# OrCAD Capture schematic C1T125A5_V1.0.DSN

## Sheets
1 001_MainChip: size A4; title: Telink-Semi; rev: V1.0A; note: C1T125A5
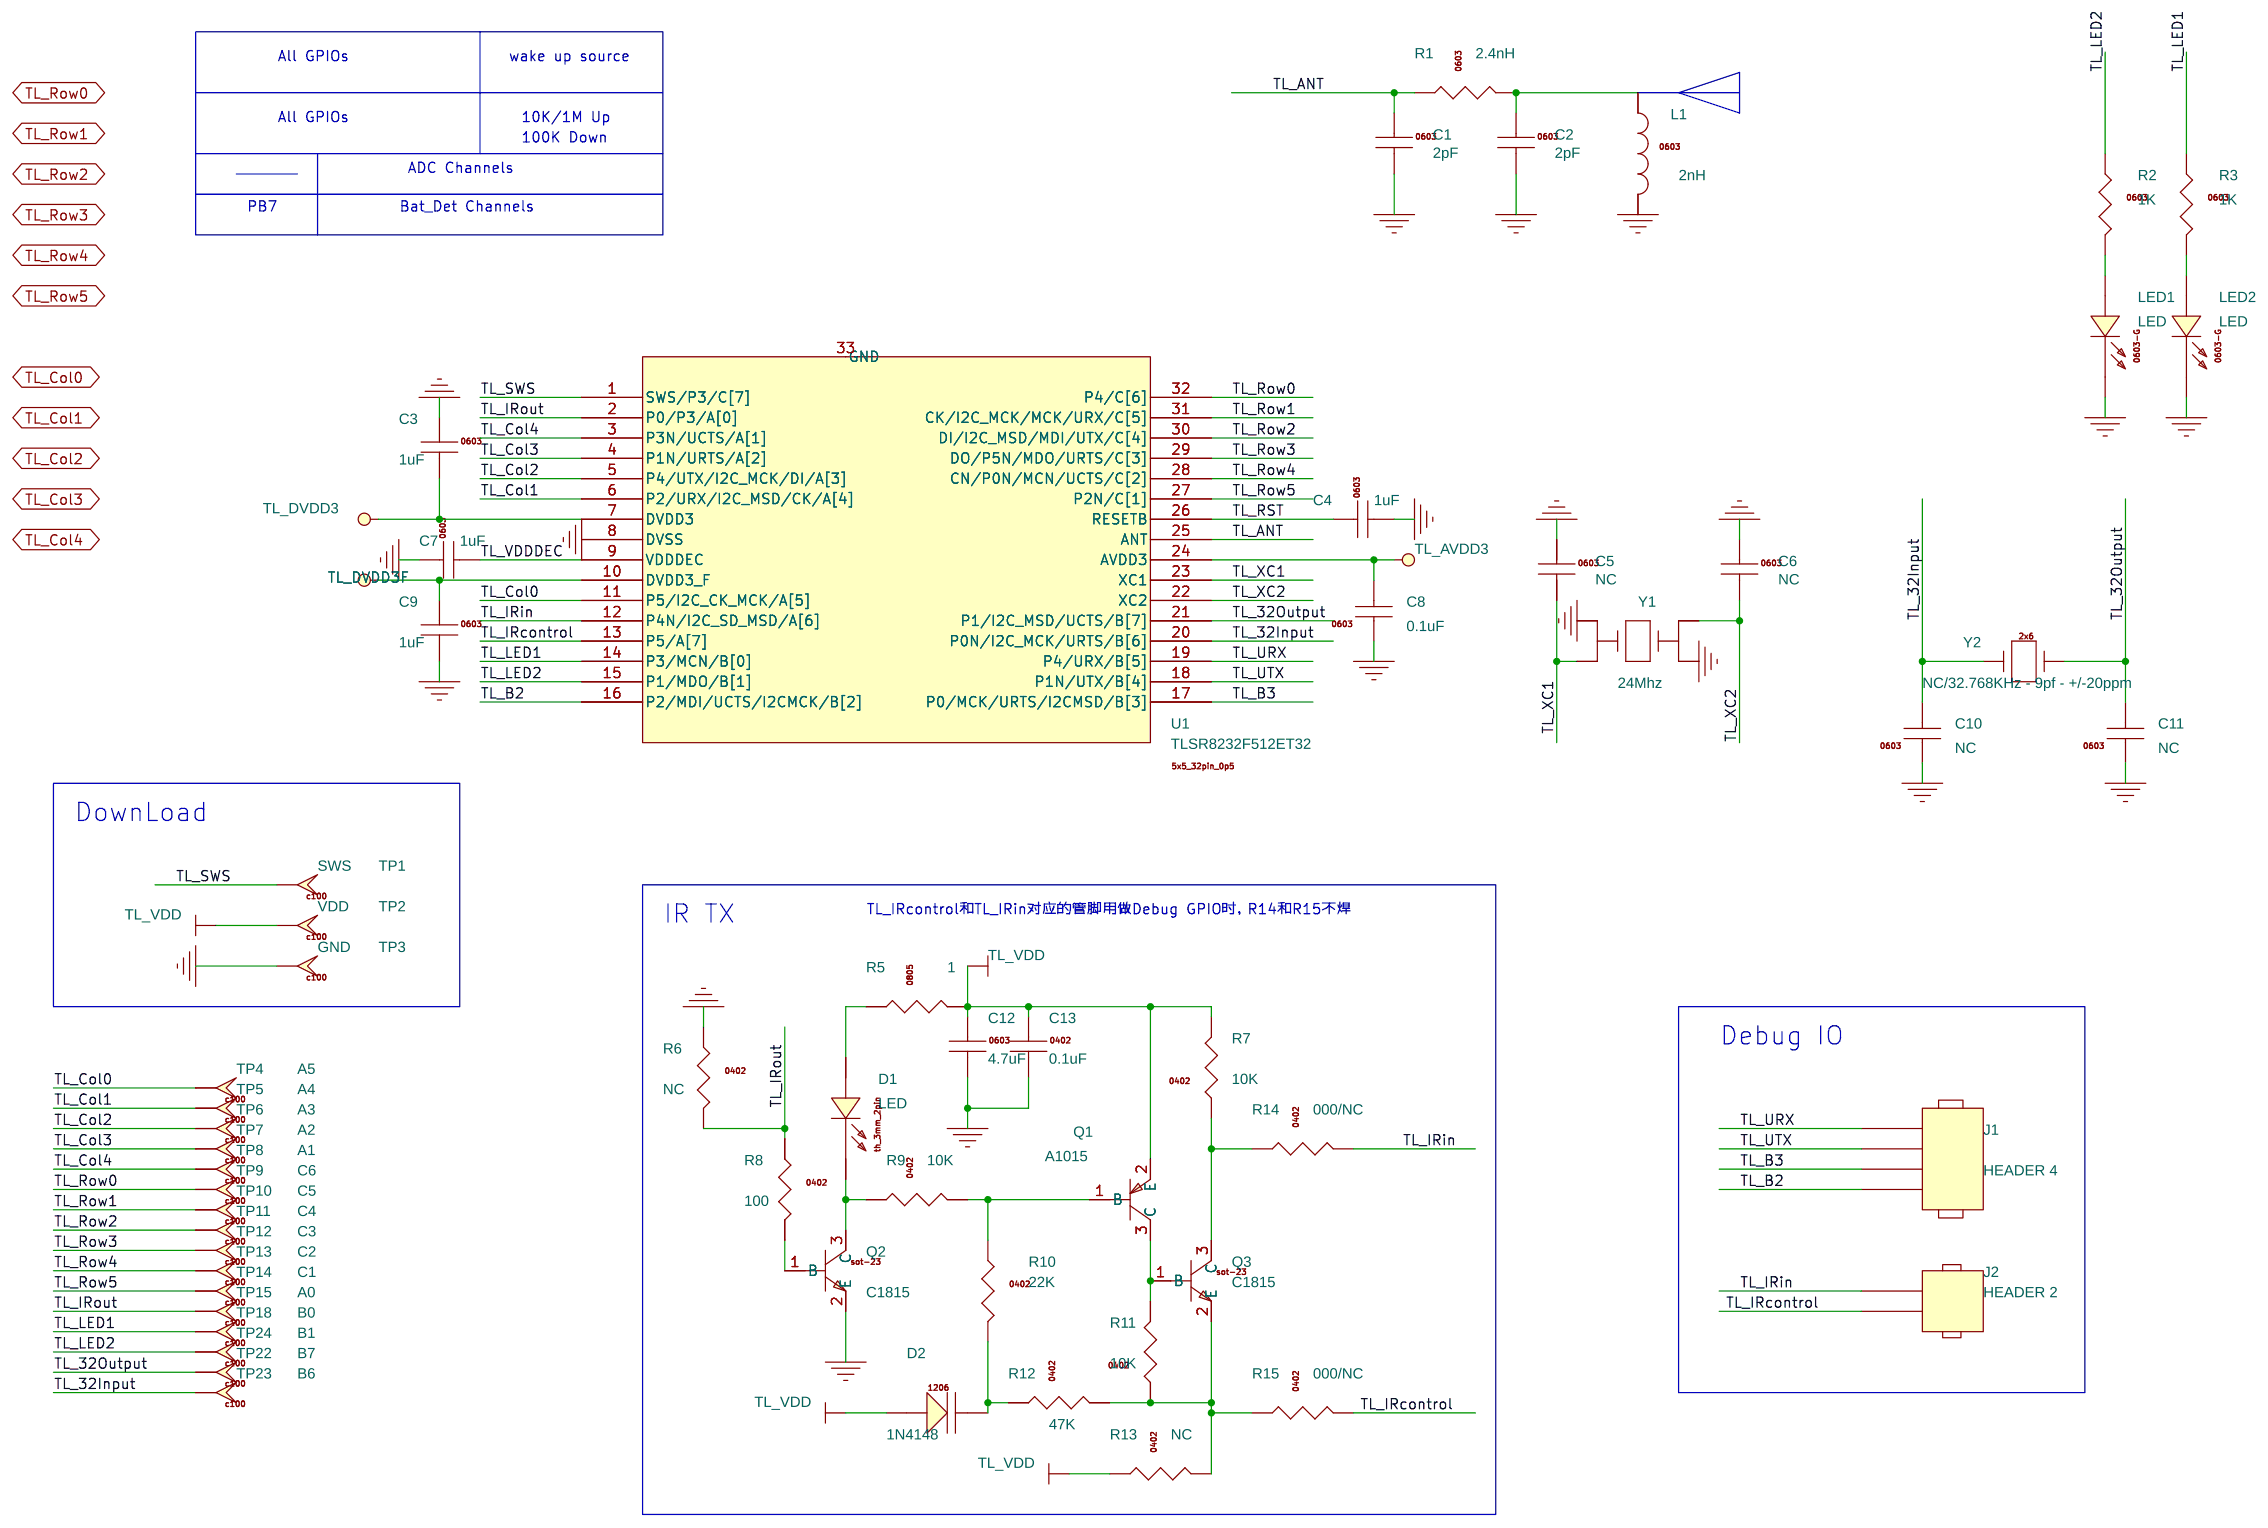
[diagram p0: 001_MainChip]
2 002_key: size A
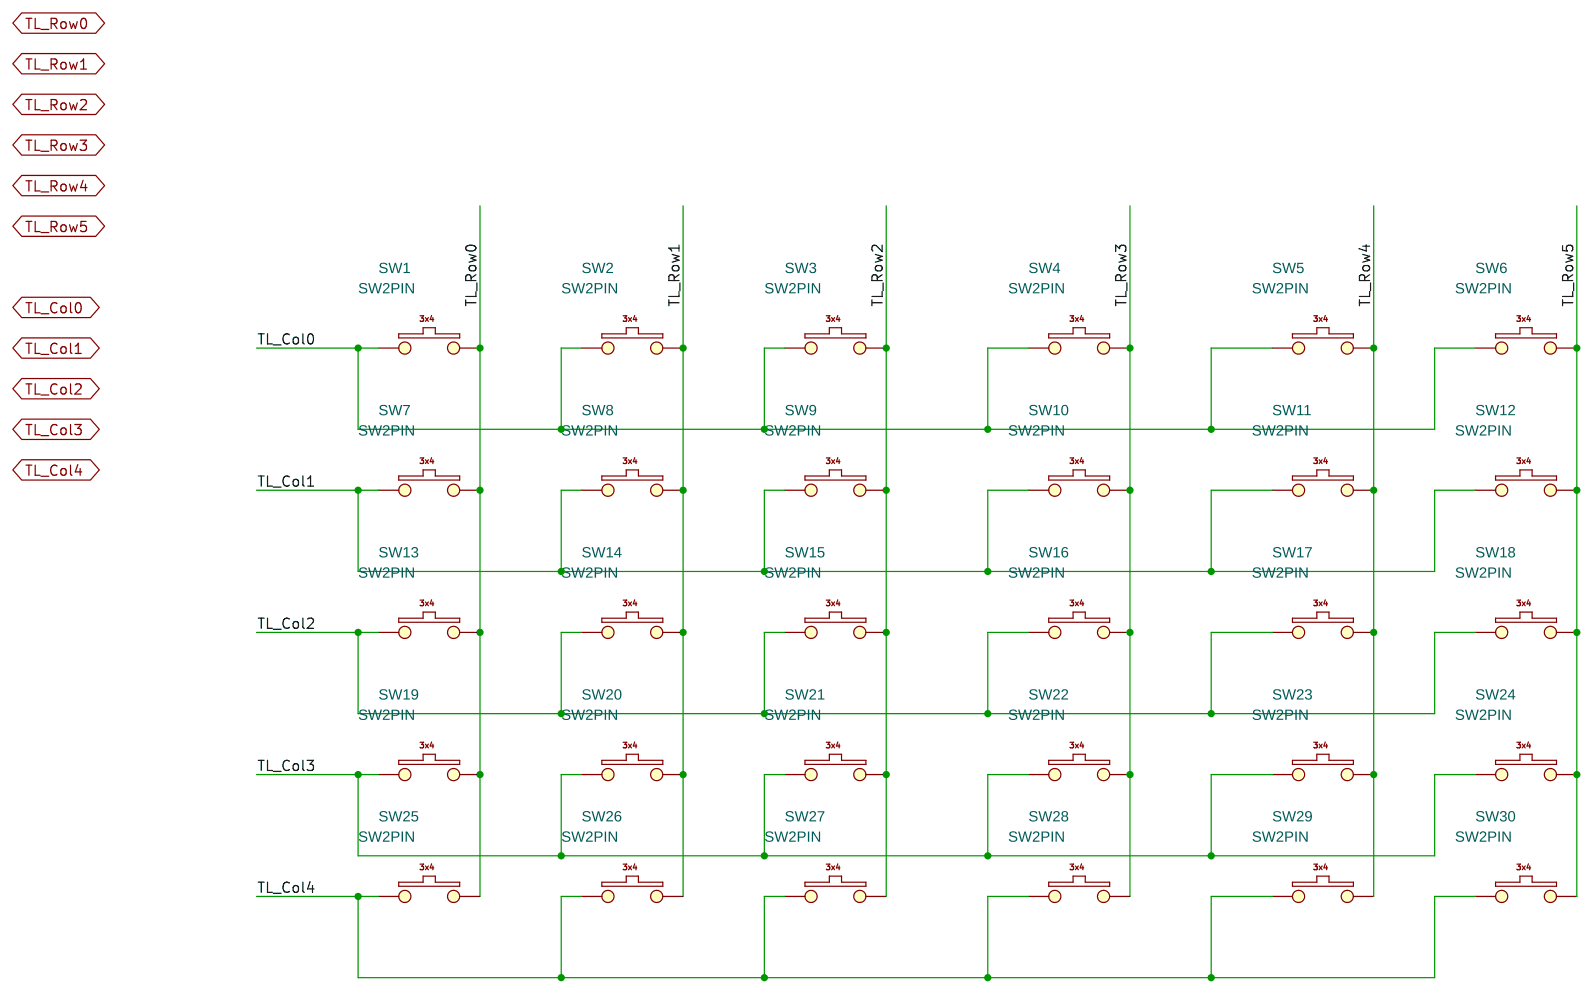
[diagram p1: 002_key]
3 003_Power: size A
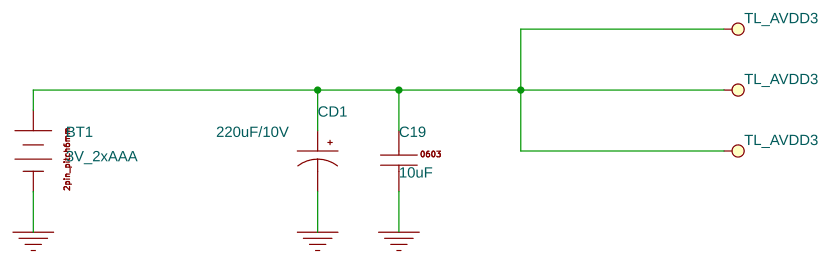
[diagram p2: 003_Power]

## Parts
sheet 001_MainChip
C1  2pF  [0402]
C2  2pF  [0402]
C3  1uF  [0603c]
C4  1uF  [0402]
C5  NC  [0402]
C6  NC  [0402]
C7  1uF  [0402]
C8  0.1uF  [0402]
C9  1uF  [0402]
C10  NC  [0402]
C11  NC  [0402]
C12  4.7uF  [0402]
C13  0.1uF  [0402]
D1  LED  [led_th_2p54mm_2pin]
D2  1N4148  [SOD80]
J1  HEADER 4  [hdr254f-1x4x850]
J2  HEADER 2  [hdr254f-1x2x850]
L1  2nH  [0402]
LED1  LED  [0603-LED]
LED2  LED  [0603-LED]
Q1  A1015  [SOT-23]
Q2  C1815  [SOT-23]
Q3  C1815  [SOT-23]
R1  2.4nH  [0402]
R2  1K  [0402]
R3  1K  [0402]
R5  1  [0402]
R6  NC  [0402]
R7  10K  [0402]
R8  100  [0402]
R9  10K  [0402]
R10  22K  [0402]
R11  10K  [0402]
R12  47K  [0402]
R13  NC  [0402]
R14  000/NC  [0402]
R15  000/NC  [0402]
TP1  SWS  [tp100]
TP2  VDD  [tp100]
TP3  GND  [tp100]
TP4  A5  [TP100]
TP5  A4  [TP100]
TP6  A3  [TP100]
TP7  A2  [TP100]
TP8  A1  [TP100]
TP9  C6  [TP100]
TP10  C5  [TP100]
TP11  C4  [TP100]
TP12  C3  [TP100]
TP13  C2  [TP100]
TP14  C1  [TP100]
TP15  A0  [TP100]
TP18  B0  [TP100]
TP22  B7  [TP100]
TP23  B6  [TP100]
TP24  B1  [TP100]
U1  TLSR8232F512ET32  [qfn_5x5_32pin_0p5_2p50x2p50]
Y1  24Mhz  [osccc250x320x110]
Y2  NC/32.768KHz - 9pf - +/-20ppm  [OSC_2x6]
sheet 002_key
SW1  SW2PIN  [sw_out6_in3]
SW2  SW2PIN  [sw_out6_in3]
SW3  SW2PIN  [sw_out6_in3]
SW4  SW2PIN  [sw_out6_in3]
SW5  SW2PIN  [sw_out6_in3]
SW6  SW2PIN  [sw_out6_in3]
SW7  SW2PIN  [sw_out6_in3]
SW8  SW2PIN  [sw_out6_in3]
SW9  SW2PIN  [sw_out6_in3]
SW10  SW2PIN  [sw_out6_in3]
SW11  SW2PIN  [sw_out6_in3]
SW12  SW2PIN  [sw_out6_in3]
SW13  SW2PIN  [sw_out6_in3]
SW14  SW2PIN  [sw_out6_in3]
SW15  SW2PIN  [sw_out6_in3]
SW16  SW2PIN  [sw_out6_in3]
SW17  SW2PIN  [sw_out6_in3]
SW18  SW2PIN  [sw_out6_in3]
SW19  SW2PIN  [sw_out6_in3]
SW20  SW2PIN  [sw_out6_in3]
SW21  SW2PIN  [sw_out6_in3]
SW22  SW2PIN  [sw_out6_in3]
SW23  SW2PIN  [sw_out6_in3]
SW24  SW2PIN  [sw_out6_in3]
SW25  SW2PIN  [sw_out6_in3]
SW26  SW2PIN  [sw_out6_in3]
SW27  SW2PIN  [sw_out6_in3]
SW28  SW2PIN  [sw_out6_in3]
SW29  SW2PIN  [sw_out6_in3]
SW30  SW2PIN  [sw_out6_in3]
sheet 003_Power
BT1  3V_2xAAA  [bat_2dip]
C19  10uF  [0603c]
CD1  220uF/10V  [cd2p0_4p0b]

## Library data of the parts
C1 C2 C5 C6 C10 C11 = C1608_NC
C3 C4 C7-C9 = C1608X5R1C105M
C12 = C1608X5R1A226M
C13 = C1005X5R1C104K
D1 = Led_Th_3mm_1
D2 = Diode_1N4148
J1 = HEADER_4
J2 = HEADER_2
L1 = MLK1608_000R
LED1 LED2 = 0603D_Green
Q1 = PNP_A1015
Q2 Q3 = NPN_C1815
R1 = RS0603K000JT
R2 R3 = RS0603K102JT
R5 = RS0805K1R0JT
R6 R13-R15 = RS0402_NC
R7 R9 R11 = RS0402K103JT
R8 = RS0402K101JT
R10 = RS0402K223JT
R12 = RS0402K473JT
TP1-TP15 TP18 TP22-TP24 = TestPad100
U1 = TLSR8232F512ET32
Y1 = CRYSTAL4_SM_0
Y2 = OSC_2x6_2pin_16Mhz
SW1-SW30 = SW2PIN_0
BT1 = BATTERY_2xAAA_3V
C19 = C1608X5R0J106M
CD1 = CD_220uF_16V

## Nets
GND: BT1.2(-) C1.2 C2.2 C3.1 C4.2 C5.1 C6.1 C7.1 C8.1 C9.2 C10.1 C11.1 C12.2 C13.2 C19.2 CD1.2 L1.2 LED1.C(CATHODE) LED2.C(CATHODE) Q2.2(E) R6.1 TP3.1(TP) U1.8(DVSS) U1.33(GND) Y1.2 Y1.4
TL_32Input: C10.2 TP23.1(TP) U1.20(P0N/I2C_MCK/URTS/B[6]) Y2.1
TL_32Output: C11.2 TP22.1(TP) U1.21(P1/I2C_MSD/UCTS/B[7]) Y2.2
TL_ANT: C1.1 R1.1 U1.25(ANT)
TL_AVDD3: BT1.1(+) C3.2 C8.2 C12.1 C13.1 C19.1 CD1.1 D2.A Q1.2(E) R5.2 R7.2 R13.1 TP2.1(TP) U1.7(DVDD3) U1.24(AVDD3)
TL_B2: J1.1 U1.16(P2/MDI/UCTS/I2CMCK/B[2])
TL_B3: J1.2 U1.17(P0/MCK/URTS/I2CMSD/B[3])
TL_Col0: TP4.1(TP) U1.11(P5/I2C_CK_MCK/A[5])
TL_Col0 (page 002_key): SW1.1 SW2.1 SW3.1 SW4.1 SW5.1 SW6.1
TL_Col1: TP5.1(TP) U1.6(P2/URX/I2C_MSD/CK/A[4])
TL_Col1 (page 002_key): SW7.1 SW8.1 SW9.1 SW10.1 SW11.1 SW12.1
TL_Col2: TP6.1(TP) U1.5(P4/UTX/I2C_MCK/DI/A[3])
TL_Col2 (page 002_key): SW13.1 SW14.1 SW15.1 SW16.1 SW17.1 SW18.1
TL_Col3: TP7.1(TP) U1.4(P1N/URTS/A[2])
TL_Col3 (page 002_key): SW19.1 SW20.1 SW21.1 SW22.1 SW23.1 SW24.1
TL_Col4: TP8.1(TP) U1.3(P3N/UCTS/A[1])
TL_Col4 (page 002_key): SW25.1 SW26.1 SW27.1 SW28.1 SW29.1 SW30.1
TL_DVDD3F: C9.1 U1.10(DVDD3_F)
TL_IRcontrol: J2.2 R15.2 U1.13(P5/A[7])
TL_IRin: J2.1 R14.2 U1.12(P4N/I2C_SD_MSD/A[6])
TL_IRout: R6.2 R8.1 TP15.1(TP) U1.2(P0/P3/A[0])
TL_LED1: R3.1 TP18.1(TP) U1.14(P3/MCN/B[0])
TL_LED2: R2.1 TP24.1(TP) U1.15(P1/MDO/B[1])
TL_Row0: TP9.1(TP) U1.32(P4/C[6])
TL_Row0 (page 002_key): SW1.2 SW7.2 SW13.2 SW19.2 SW25.2
TL_Row1: TP10.1(TP) U1.31(CK/I2C_MCK/MCK/URX/C[5])
TL_Row1 (page 002_key): SW2.2 SW8.2 SW14.2 SW20.2 SW26.2
TL_Row2: TP11.1(TP) U1.30(DI/I2C_MSD/MDI/UTX/C[4])
TL_Row2 (page 002_key): SW3.2 SW9.2 SW15.2 SW21.2 SW27.2
TL_Row3: TP12.1(TP) U1.29(DO/P5N/MDO/URTS/C[3])
TL_Row3 (page 002_key): SW4.2 SW10.2 SW16.2 SW22.2 SW28.2
TL_Row4: TP13.1(TP) U1.28(CN/P0N/MCN/UCTS/C[2])
TL_Row4 (page 002_key): SW5.2 SW11.2 SW17.2 SW23.2 SW29.2
TL_Row5: TP14.1(TP) U1.27(P2N/C[1])
TL_Row5 (page 002_key): SW6.2 SW12.2 SW18.2 SW24.2 SW30.2
TL_RST: C4.1 U1.26(RESETB)
TL_SWS: TP1.1(TP) U1.1(SWS/P3/C[7])
TL_URX: J1.4 U1.19(P4/URX/B[5])
TL_UTX: J1.3 U1.18(P1N/UTX/B[4])
TL_VDDDEC: C7.2 U1.9(VDDDEC)
TL_XC1: C5.2 U1.23(XC1) Y1.3
TL_XC2: C6.2 U1.22(XC2) Y1.1
N14595282: C2.1 L1.1 R1.2
N14596477: LED2.A(ANODE) R3.2
N14596527: LED1.A(ANODE) R2.2
N14600673: Q3.2(E) R11.1 R12.2 R13.2 R15.1
N14600711: D1.A(ANODE) R5.1
N14600791: D2.C R10.2 R12.1
N14601003: Q2.1(B) R8.2
N14601035: D1.C(CATHODE) Q2.3(C) R9.1
N14601075: Q1.3(C) Q3.1(B) R11.2
N14601095: Q1.1(B) R9.2 R10.1
N14601159: Q3.3(C) R7.1 R14.1

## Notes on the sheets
sheet 1
- All GPIOs
- wake up source
- All GPIOs
- 10K/1M Up
- 100K Down
- ADC Channels
- PB7
- Bat_Det Channels
- DownLoad
- IR TX
- TL_IRcontrol和TL_IRin对应的管脚用做Debug GPIO时，R14和R15不焊
- Debug IO
